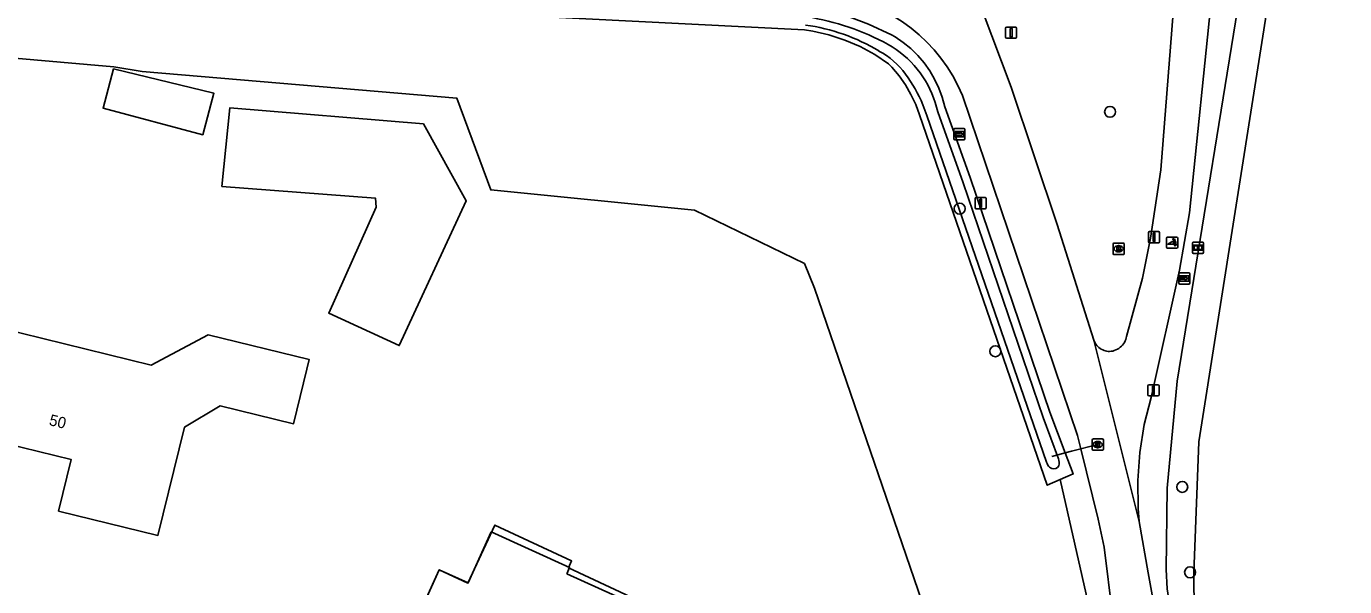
# Model space of a CAD drawing. Extents: x 162722 to 165099, y 384721 to 386283.
# Drawn here: x 164061.3 to 164178.9, y 385180.3 to 385230.3 of the extents above; entities that cross this region are included whole.
import ezdxf

# ---------------------------------------------------------------- set-up
doc = ezdxf.new("R2010")
doc.units = 0
for name, color, linetype in [('IMGEO_Afsluitpaal', 7, 'Continuous'), ('IMGEO_Boom', 7, 'Continuous'), ('IMGEO_Brandkraan', 7, 'Continuous'), ('IMGEO_Duiker', 7, 'Continuous'), ('IMGEO_Gemengd_bos', 7, 'Continuous'), ('IMGEO_Groenvoorziening', 7, 'Continuous'), ('IMGEO_Informatiebord', 7, 'Continuous'), ('IMGEO_Pand', 7, 'Continuous'), ('IMGEO_Pand_nummerreeks', 7, 'Continuous'), ('IMGEO_Pand_vergunning_verleend', 7, 'Continuous'), ('IMGEO_Poller', 7, 'Continuous'), ('IMGEO_Rioolput', 7, 'Continuous'), ('IMGEO_Verkeersbordpaal', 7, 'Continuous'), ('IMGEO_Voetpad_halfverhard', 7, 'Continuous'), ('IMGEO_Waterloop', 7, 'Continuous'), ('IMGEO_Wegwijzer', 7, 'Continuous')]:
    doc.layers.add(name, color=color, linetype=linetype)

msp = doc.modelspace()

# ---------------------------------------------------------------- linework, layer by layer
at = {"layer": 'IMGEO_Afsluitpaal'}
for p, q in [((164148.67, 385229.32), (164148.67, 385230.12)), ((164148.67, 385230.12), (164148.67, 385229.32)), ((164148.77, 385230.22), (164149.55, 385230.22)), ((164149.55, 385230.22), (164148.77, 385230.22)), ((164149.65, 385230.12), (164149.65, 385229.32)), ((164149.65, 385229.32), (164149.65, 385230.12)), ((164149.55, 385229.22), (164148.77, 385229.22)), ((164148.77, 385229.22), (164149.55, 385229.22)), ((164145.94, 385214.1), (164145.94, 385214.9)), ((164145.94, 385214.9), (164145.94, 385214.1)), ((164146.04, 385215), (164146.83, 385215)), ((164146.83, 385215), (164146.04, 385215)), ((164146.93, 385214.9), (164146.93, 385214.1)), ((164146.93, 385214.1), (164146.93, 385214.9)), ((164146.83, 385214), (164146.04, 385214)), ((164146.04, 385214), (164146.83, 385214)), ((164161.42, 385211.06), (164161.42, 385211.86)), ((164161.42, 385211.86), (164161.42, 385211.06)), ((164161.52, 385211.96), (164162.31, 385211.96)), ((164162.31, 385211.96), (164161.52, 385211.96)), ((164162.31, 385210.96), (164161.52, 385210.96)), ((164161.52, 385210.96), (164162.31, 385210.96)), ((164162.41, 385211.86), (164162.41, 385211.06)), ((164162.41, 385211.06), (164162.41, 385211.86))]:
    msp.add_line(p, q, dxfattribs=at)
for points in [[(164149.08, 385230.09), (164149.24, 385230.09), (164149.24, 385229.34), (164149.08, 385229.34), (164149.08, 385230.09)], [(164146.36, 385214.87), (164146.51, 385214.87), (164146.51, 385214.12), (164146.36, 385214.12), (164146.36, 385214.87)], [(164161.84, 385211.83), (164161.99, 385211.83), (164161.99, 385211.08), (164161.84, 385211.08), (164161.84, 385211.83)]]:
    msp.add_lwpolyline(points, dxfattribs=at)
for centre, start, end in [((164148.77, 385230.12), 90, 180), ((164148.77, 385230.12), 90, 180), ((164149.55, 385230.12), 0, 90), ((164149.55, 385230.12), 360, 90), ((164148.77, 385229.32), 180, 270), ((164148.77, 385229.32), 180, 270), ((164149.55, 385229.32), 270, 0), ((164149.55, 385229.32), 270, 0), ((164146.04, 385214.9), 90, 180), ((164146.04, 385214.9), 90, 180), ((164146.83, 385214.9), 0, 90), ((164146.83, 385214.9), 360, 90), ((164146.04, 385214.1), 180, 270), ((164146.04, 385214.1), 180, 270), ((164146.83, 385214.1), 270, 0), ((164146.83, 385214.1), 270, 0), ((164161.52, 385211.86), 90, 180), ((164161.52, 385211.86), 90, 180), ((164161.52, 385211.06), 180, 270), ((164161.52, 385211.06), 180, 270), ((164162.31, 385211.86), 0, 90), ((164162.31, 385211.86), 360, 90), ((164162.31, 385211.06), 270, 0), ((164162.31, 385211.06), 270, 0)]:
    msp.add_arc(centre, 0.1, start, end, dxfattribs=at)
at = {"layer": 'IMGEO_Boom'}
for centre in [(164157.99, 385222.65), (164144.57, 385214.01), (164147.75, 385201.28), (164164.43, 385189.17), (164165.13, 385181.55)]:
    msp.add_circle(centre, 0.489, dxfattribs=at)
at = {"layer": 'IMGEO_Brandkraan'}
for p, q in [((164158.33, 385210.93), (164159.18, 385210.93)), ((164158.26, 385210), (164158.26, 385210.86)), ((164159.18, 385209.93), (164158.33, 385209.93)), ((164158.74, 385210.71), (164158.77, 385210.71)), ((164158.77, 385210.15), (164158.74, 385210.15)), ((164159.26, 385210.86), (164159.26, 385210))]:
    msp.add_line(p, q, dxfattribs=at)
for points in [[(164158.33, 385210.93), (164159.18, 385210.93)], [(164158.26, 385210), (164158.26, 385210.86)], [(164159.18, 385209.93), (164158.33, 385209.93)], [(164158.6, 385210.63), (164158.6, 385210.23), (164158.82, 385210.23)], [(164158.84, 385210.63), (164158.6, 385210.63)], [(164158.78, 385210.55), (164158.73, 385210.55), (164158.73, 385210.47)], [(164158.73, 385210.47), (164158.78, 385210.47)], [(164158.79, 385210.4), (164158.73, 385210.4), (164158.73, 385210.31)], [(164158.73, 385210.31), (164158.79, 385210.31)], [(164159.26, 385210.86), (164159.26, 385210)]]:
    msp.add_lwpolyline(points, dxfattribs=at)
for centre, radius, start, end in [((164158.33, 385210.85), 0.0765, 91.552, 178.448), ((164158.33, 385210.85), 0.0765, 91.552, 178.448), ((164159.18, 385210.85), 0.0765, 1.552, 88.448), ((164159.18, 385210.85), 0.0765, 1.552, 88.448), ((164158.33, 385210), 0.0765, 181.552, 268.448), ((164158.33, 385210), 0.0765, 181.552, 268.448), ((164158.78, 385210.51), 0.0379, 267.8285, 90.9355), ((164158.79, 385210.36), 0.0404, 269.8759, 90.5077), ((164158.82, 385210.48), 0.251, 268.6676, 293.5347), ((164158.84, 385210.48), 0.145, 59.4692, 91.5367), ((164158.86, 385210.53), 0.0922, 285.5137, 58.1501), ((164158.87, 385210.34), 0.105, 301.3115, 78.989), ((164159.18, 385210), 0.0765, 271.552, 358.448), ((164159.18, 385210), 0.0765, 271.552, 358.448)]:
    msp.add_arc(centre, radius, start, end, dxfattribs=at)
for centre, major_axis, ratio, start_param, end_param in [((164158.74, 385210.43), (-0.387, 0.002), 0.722429, 4.712389, 7.853982), ((164158.77, 385210.43), (-0.39, 0.002), 0.717154, 1.570796, 4.712389)]:
    msp.add_ellipse(centre, major_axis=major_axis, ratio=ratio, start_param=start_param, end_param=end_param, dxfattribs=at)
at = {"layer": 'IMGEO_Duiker'}
msp.add_lwpolyline([(164152.79, 385191.9), (164153.99, 385192.21), (164154.55, 385192.35), (164156.89, 385192.95)], dxfattribs=at)
at = {"layer": 'IMGEO_Gemengd_bos'}
for points in [[(164153.54, 385189.83), (164152.38, 385189.32), (164140.97, 385222.37), (164140.64, 385223.3), (164140.22, 385224.2), (164139.73, 385225.06), (164139.16, 385225.87), (164138.52, 385226.63), (164138.22, 385226.95), (164136.98, 385227.77), (164135.68, 385228.48), (164134.31, 385229.06), (164132.9, 385229.53), (164131.45, 385229.86), (164130.71, 385229.98), (164100.55, 385231.49), (164022.81, 385237.41), (164009.25, 385237.64), (164000, 385238.42), (163921.82, 385245)], [(164099.32, 385152.4), (164101.92, 385153.63), (164120.43, 385163.47), (164142.64, 385174.73), (164131.6, 385206.91), (164130.71, 385209.11), (164120.89, 385213.87), (164102.71, 385215.68), (164099.68, 385223.88), (164071.61, 385226.26), (164069.06, 385226.66), (164000.03, 385232.74), (163994.49, 385233.42), (163921.24, 385240.04)], [(164156.39, 385175.57), (164156.16, 385178.15), (164156.15, 385178.3), (164153.54, 385189.83)]]:
    msp.add_lwpolyline(points, dxfattribs=at)
at = {"layer": 'IMGEO_Groenvoorziening'}
msp.add_lwpolyline([(164131, 385232.07), (164132.15, 385231.85), (164134.32, 385231.27), (164136.44, 385230.49), (164138.47, 385229.53), (164138.8, 385229.34), (164139.52, 385228.85), (164140.2, 385228.3), (164140.82, 385227.69), (164141.39, 385227.03), (164141.89, 385226.32), (164142.33, 385225.56), (164142.7, 385224.77), (164143, 385223.95), (164143.23, 385223.11), (164145.49, 385216.79), (164152.62, 385195.85), (164153.99, 385192.21), (164154.7, 385190.33), (164153.54, 385189.83)], dxfattribs=at)
at = {"layer": 'IMGEO_Informatiebord'}
for p, q in [((164165.34, 385210.12), (164165.34, 385210.92)), ((164165.34, 385210.92), (164165.34, 385210.12)), ((164165.44, 385211.02), (164166.23, 385211.02)), ((164166.23, 385211.02), (164165.44, 385211.02)), ((164166.33, 385210.92), (164166.33, 385210.12)), ((164166.33, 385210.12), (164166.33, 385210.92)), ((164166.23, 385210.02), (164165.44, 385210.02)), ((164165.44, 385210.02), (164166.23, 385210.02))]:
    msp.add_line(p, q, dxfattribs=at)
for points in [[(164165.44, 385210.75), (164166.23, 385210.75), (164166.23, 385210.29), (164165.44, 385210.29), (164165.44, 385210.75)], [(164165.51, 385210.69), (164165.51, 385210.35), (164165.78, 385210.35), (164165.78, 385210.57), (164165.89, 385210.57), (164165.89, 385210.35), (164166.17, 385210.35), (164166.17, 385210.69), (164165.89, 385210.69), (164165.89, 385210.61), (164165.78, 385210.61), (164165.79, 385210.69), (164165.51, 385210.69)]]:
    msp.add_lwpolyline(points, dxfattribs=at)
for centre, start, end in [((164165.44, 385210.92), 90, 180), ((164165.44, 385210.92), 90, 180), ((164166.23, 385210.92), 0, 90), ((164166.23, 385210.92), 360, 90), ((164165.44, 385210.12), 180, 270), ((164165.44, 385210.12), 180, 270), ((164166.23, 385210.12), 270, 0), ((164166.23, 385210.12), 270, 0)]:
    msp.add_arc(centre, 0.1, start, end, dxfattribs=at)
at = {"layer": 'IMGEO_Pand'}
for points in [[(164069.04, 385226.5), (164078, 385224.31), (164077.01, 385220.61), (164068.11, 385222.99), (164069.04, 385226.5)], [(164056.48, 385193.77), (164057.68, 385198.62), (164058.84, 385203.37), (164072.42, 385200.03), (164077.49, 385202.76), (164086.52, 385200.54), (164086.3, 385199.67), (164085.11, 385194.81), (164078.55, 385196.42), (164075.39, 385194.51), (164073.01, 385184.84), (164064.14, 385187.01), (164065.27, 385191.61), (164056.48, 385193.77)], [(164109.49, 385181.41), (164109.75, 385181.99), (164102.76, 385185.15), (164100.7, 385180.6), (164098.12, 385181.77), (164095.65, 385176.31), (164093.59, 385171.75), (164101.34, 385168.24), (164103.25, 385172.46), (164105.63, 385171.38), (164105.36, 385170.8), (164111.17, 385168.16), (164113.64, 385173.62), (164124.56, 385168.68), (164126.78, 385173.58), (164109.49, 385181.41)]]:
    msp.add_lwpolyline(points, dxfattribs=at)
at = {"layer": 'IMGEO_Pand_vergunning_verleend'}
for points in [[(164078.71, 385215.99), (164079.44, 385223.02), (164096.7, 385221.58), (164100.53, 385214.7), (164094.55, 385201.78), (164088.26, 385204.69), (164092.49, 385214.14), (164092.43, 385214.93), (164078.71, 385215.99)], [(164093.59, 385171.75), (164098.12, 385181.77), (164100.66, 385180.58), (164103.08, 385185.76), (164109.93, 385182.56), (164109.64, 385181.94), (164126.7, 385173.98), (164124.55, 385169.23), (164113.85, 385174.08), (164111.17, 385168.16), (164105.36, 385170.8), (164105.63, 385171.38), (164103.25, 385172.46), (164101.34, 385168.24), (164093.59, 385171.75)]]:
    msp.add_lwpolyline(points, dxfattribs=at)
at = {"layer": 'IMGEO_Poller'}
for p, q in [((164163.03, 385211.37), (164163.03, 385210.57)), ((164163.03, 385211.37), (164163.03, 385210.57)), ((164163.93, 385211.47), (164163.13, 385211.47)), ((164163.93, 385211.47), (164163.13, 385211.47)), ((164164.03, 385210.57), (164164.03, 385211.37)), ((164164.03, 385210.57), (164164.03, 385211.37)), ((164163.13, 385210.47), (164163.93, 385210.47)), ((164163.13, 385210.47), (164163.93, 385210.47))]:
    msp.add_line(p, q, dxfattribs=at)
for points in [[(164163.67, 385210.83), (164163.15, 385210.83), (164163.58, 385211.1)], [(164163.71, 385211.2), (164163.7, 385211.13), (164163.57, 385211.33)], [(164163.57, 385211.33), (164163.8, 385211.26), (164163.73, 385211.23)], [(164163.73, 385210.65), (164163.79, 385210.88), (164163.82, 385210.82)], [(164163.86, 385210.79), (164163.93, 385210.78), (164163.73, 385210.65)]]:
    msp.add_lwpolyline(points, dxfattribs=at)
for centre, radius, start, end in [((164163.13, 385211.37), 0.0946, 90, 180), ((164163.13, 385211.37), 0.0946, 90, 180), ((164163.34, 385210.88), 0.332, 351.3247, 42.4854), ((164163.35, 385210.88), 0.476, 351.7527, 41.1691), ((164163.35, 385210.88), 0.516, 349.3569, 42.2912), ((164163.93, 385211.37), 0.0946, 0, 90), ((164163.93, 385211.37), 0.0946, 0, 90), ((164163.13, 385210.57), 0.0946, 180, 270), ((164163.13, 385210.57), 0.0946, 180, 270), ((164163.93, 385210.57), 0.0946, 270, 0), ((164163.93, 385210.57), 0.0946, 270, 0)]:
    msp.add_arc(centre, radius, start, end, dxfattribs=at)
at = {"layer": 'IMGEO_Rioolput'}
for p, q in [((164156.39, 385192.52), (164156.39, 385193.37)), ((164156.47, 385193.45), (164157.32, 385193.45)), ((164156.88, 385193.23), (164156.91, 385193.23)), ((164157.39, 385193.37), (164157.39, 385192.52)), ((164157.32, 385192.45), (164156.47, 385192.45)), ((164156.9, 385192.67), (164156.88, 385192.67))]:
    msp.add_line(p, q, dxfattribs=at)
for points in [[(164156.39, 385192.52), (164156.39, 385193.37)], [(164156.47, 385193.45), (164157.32, 385193.45)], [(164157.39, 385193.37), (164157.39, 385192.52)], [(164157.32, 385192.45), (164156.47, 385192.45)], [(164156.98, 385193.14), (164156.73, 385193.15), (164156.73, 385192.75)], [(164156.73, 385192.75), (164156.85, 385192.75), (164156.85, 385192.91), (164156.86, 385192.91)], [(164156.91, 385193.07), (164156.85, 385193.07), (164156.85, 385192.98)], [(164156.85, 385192.98), (164156.9, 385192.98)], [(164156.91, 385192.88), (164156.98, 385192.75), (164157.12, 385192.75), (164157.06, 385192.87)]]:
    msp.add_lwpolyline(points, dxfattribs=at)
for centre, radius, start, end in [((164156.47, 385193.37), 0.0765, 91.552, 178.448), ((164156.47, 385193.37), 0.0765, 91.552, 178.448), ((164157.32, 385193.37), 0.0765, 1.552, 88.448), ((164157.32, 385193.37), 0.0765, 1.552, 88.448), ((164156.47, 385192.52), 0.0765, 181.552, 268.448), ((164156.47, 385192.52), 0.0765, 181.552, 268.448), ((164156.86, 385192.86), 0.0533, 26.0293, 88.6989), ((164156.89, 385193.17), 0.19, 274.7715, 282.9687), ((164156.91, 385192.97), 0.0964, 77.0061, 93.1865), ((164156.93, 385193.03), 0.0378, 276.6634, 79.6772), ((164156.98, 385193.04), 0.109, 350.3612, 89.416), ((164156.98, 385193.03), 0.112, 277.5842, 350.9817), ((164156.96, 385192.82), 0.108, 29.5134, 73.7905), ((164157.32, 385192.52), 0.0765, 271.552, 358.448), ((164157.32, 385192.52), 0.0765, 271.552, 358.448)]:
    msp.add_arc(centre, radius, start, end, dxfattribs=at)
for centre, major_axis, ratio, start_param, end_param in [((164156.88, 385192.95), (-0.387, 0.002), 0.722429, 4.712389, 7.853982), ((164156.9, 385192.95), (-0.39, 0.002), 0.717154, 1.570796, 4.712389)]:
    msp.add_ellipse(centre, major_axis=major_axis, ratio=ratio, start_param=start_param, end_param=end_param, dxfattribs=at)
at = {"layer": 'IMGEO_Verkeersbordpaal'}
for p, q in [((164161.37, 385197.39), (164161.37, 385198.19)), ((164161.37, 385198.19), (164161.37, 385197.39)), ((164161.47, 385198.29), (164162.26, 385198.29)), ((164162.26, 385198.29), (164161.47, 385198.29)), ((164162.36, 385198.19), (164162.36, 385197.39)), ((164162.36, 385197.39), (164162.36, 385198.19)), ((164162.26, 385197.29), (164161.47, 385197.29)), ((164161.47, 385197.29), (164162.26, 385197.29))]:
    msp.add_line(p, q, dxfattribs=at)
msp.add_lwpolyline([(164161.79, 385198.17), (164161.94, 385198.17), (164161.94, 385197.42), (164161.79, 385197.42), (164161.79, 385198.17)], dxfattribs=at)
for centre, start, end in [((164161.47, 385198.19), 90, 180), ((164161.47, 385198.19), 90, 180), ((164162.26, 385198.19), 0, 90), ((164162.26, 385198.19), 360, 90), ((164161.47, 385197.39), 180, 270), ((164161.47, 385197.39), 180, 270), ((164162.26, 385197.39), 270, 0), ((164162.26, 385197.39), 270, 0)]:
    msp.add_arc(centre, 0.1, start, end, dxfattribs=at)
at = {"layer": 'IMGEO_Voetpad_halfverhard'}
for points in [[(164160.6, 385186.09), (164160.5, 385187.23), (164160.46, 385189.74), (164160.64, 385192.25), (164161.04, 385194.73), (164161.66, 385197.16), (164164.19, 385208.51), (164165.07, 385213.63), (164167.08, 385233.11), (164169.88, 385250), (164173.52, 385271.93), (164177.58, 385299.19)], [(164156.55, 385202.26), (164153.27, 385212.59), (164149.17, 385224.84), (164146.56, 385231.72), (164144.09, 385238.99), (164143.69, 385240.59)], [(164163.72, 385232.62), (164162.52, 385217.48), (164161.59, 385211.38), (164160.89, 385207.79), (164159.47, 385202.61), (164159.44, 385202.48), (164159.39, 385202.34), (164159.34, 385202.2), (164159.27, 385202.07), (164159.19, 385201.95), (164159.1, 385201.83), (164159, 385201.73), (164158.89, 385201.63), (164158.77, 385201.54), (164158.64, 385201.46), (164158.51, 385201.4), (164158.37, 385201.35), (164158.23, 385201.3), (164158.09, 385201.28), (164157.94, 385201.26), (164157.83, 385201.27), (164157.7, 385201.28), (164157.57, 385201.31), (164157.45, 385201.35), (164157.33, 385201.4), (164157.21, 385201.46), (164157.1, 385201.53), (164156.99, 385201.61), (164156.9, 385201.7), (164156.81, 385201.8), (164156.73, 385201.9), (164156.66, 385202.02), (164156.6, 385202.13), (164156.55, 385202.26)], [(164144.81, 385224.11), (164155.09, 385193.75), (164155.39, 385192.56), (164156.94, 385186.3), (164157.46, 385183.78), (164158.2, 385177.77), (164157.94, 385176.39)], [(164160.6, 385186.09), (164156.55, 385202.26)], [(164165.26, 385160.28), (164161.4, 385181.51), (164160.6, 385186.09)]]:
    msp.add_lwpolyline(points, dxfattribs=at)
msp.add_arc((164131.34, 385218.61), 14.55, 22.2135, 82.4747, dxfattribs=at)
at = {"layer": 'IMGEO_Waterloop'}
for points in [[(164170.33, 385237.69), (164163.98, 385198.6), (164163.08, 385189.07), (164162.99, 385181.81), (164163.1, 385180.06), (164163.36, 385178.32), (164163.78, 385176.6), (164166.97, 385162.03), (164167.17, 385160.48)], [(164188.95, 385170.65), (164168.39, 385162.5), (164168.33, 385163.01), (164165.86, 385176.93), (164165.62, 385178.27), (164165.47, 385179.88), (164165.46, 385181.5), (164165.91, 385193.19), (164172.57, 385235.47)], [(164141.29, 385223.29), (164141.63, 385222.33), (164152.31, 385191.39), (164152.37, 385191.25), (164152.44, 385191.12)], [(164153.39, 385191.69), (164152.01, 385195.36), (164144.88, 385216.3), (164142.61, 385222.64), (164142.38, 385223.48)]]:
    msp.add_lwpolyline(points, dxfattribs=at)
for centre, radius, start, end in [((164127.08, 385207.95), 23.51, 61.8204, 80.5618), ((164128.44, 385213.23), 17.33, 59.0227, 82.1567), ((164133.71, 385220.75), 9.09, 17.4895, 60.5249), ((164134.14, 385222), 6.88, 35.7145, 62.1058), ((164129.77, 385218.49), 12.48, 22.619, 37.0879), ((164153.01, 385191.45), 0.665, 209.9707, 249.5715), ((164152.97, 385191.32), 0.527, 248.8297, 330.7681), ((164152.26, 385191.3), 1.19, 348.5331, 19.4194)]:
    msp.add_arc(centre, radius, start, end, dxfattribs=at)
at = {"layer": 'IMGEO_Wegwijzer'}
for p, q in [((164144.04, 385220.26), (164144.04, 385221.06)), ((164144.04, 385221.06), (164144.04, 385220.26)), ((164144.14, 385221.16), (164144.93, 385221.16)), ((164144.93, 385221.16), (164144.14, 385221.16)), ((164145.03, 385221.06), (164145.03, 385220.26)), ((164145.03, 385220.26), (164145.03, 385221.06)), ((164144.93, 385220.16), (164144.14, 385220.16)), ((164144.14, 385220.16), (164144.93, 385220.16)), ((164164.12, 385207.38), (164164.12, 385208.18)), ((164164.12, 385208.18), (164164.12, 385207.38)), ((164164.22, 385208.28), (164165.01, 385208.28)), ((164165.01, 385208.28), (164164.22, 385208.28)), ((164165.11, 385208.18), (164165.11, 385207.38)), ((164165.11, 385207.38), (164165.11, 385208.18)), ((164165.01, 385207.28), (164164.22, 385207.28)), ((164164.22, 385207.28), (164165.01, 385207.28))]:
    msp.add_line(p, q, dxfattribs=at)
for points in [[(164144.15, 385220.89), (164144.93, 385220.89), (164144.93, 385220.42), (164144.15, 385220.42), (164144.15, 385220.89)], [(164144.21, 385220.74), (164144.21, 385220.66), (164144.21, 385220.57), (164144.62, 385220.57), (164144.62, 385220.49), (164144.87, 385220.66), (164144.62, 385220.82), (164144.62, 385220.74), (164144.21, 385220.74)], [(164164.22, 385208.02), (164165.01, 385208.02), (164165.01, 385207.55), (164164.22, 385207.55), (164164.22, 385208.02)], [(164164.29, 385207.87), (164164.29, 385207.78), (164164.29, 385207.7), (164164.7, 385207.7), (164164.7, 385207.62), (164164.94, 385207.78), (164164.7, 385207.95), (164164.7, 385207.87), (164164.29, 385207.87)]]:
    msp.add_lwpolyline(points, dxfattribs=at)
for centre, start, end in [((164144.14, 385221.06), 90, 180), ((164144.14, 385221.06), 90, 180), ((164144.93, 385221.06), 0, 90), ((164144.93, 385221.06), 360, 90), ((164144.14, 385220.26), 180, 270), ((164144.14, 385220.26), 180, 270), ((164144.93, 385220.26), 270, 0), ((164144.93, 385220.26), 270, 0), ((164164.22, 385208.18), 90, 180), ((164164.22, 385208.18), 90, 180), ((164164.22, 385207.38), 180, 270), ((164164.22, 385207.38), 180, 270), ((164165.01, 385208.18), 0, 90), ((164165.01, 385208.18), 360, 90), ((164165.01, 385207.38), 270, 0), ((164165.01, 385207.38), 270, 0)]:
    msp.add_arc(centre, 0.1, start, end, dxfattribs=at)

# ---------------------------------------------------------------- texts
at = {"layer": 'IMGEO_Pand_nummerreeks'}
msp.add_text('50', height=1, rotation=346.2064, dxfattribs=at).set_placement((164063.23, 385194.7))

doc.saveas('drawing.dxf')
